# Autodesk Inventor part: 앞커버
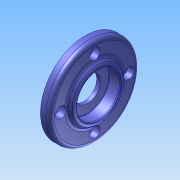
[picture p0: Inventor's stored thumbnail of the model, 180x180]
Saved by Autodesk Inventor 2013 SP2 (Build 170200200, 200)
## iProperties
Created: 2025-05
Part Number: 앞커버
Material: Generic
Document SubType Name: Modeling
Designer: a
Density: 1 g/cm^3
Author: a
변환 표준: STEP AP214IS
전처리기: Build: 200, Release: 2013 SP2 Update 6 - Date: Thu 07/17/2014
전송 단위: 밀리미터
불확실성: 0.01
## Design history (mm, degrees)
node "앞커버1"
node "솔리드1"
node "기준1"
